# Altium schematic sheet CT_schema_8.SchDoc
size 391 x 238 mm
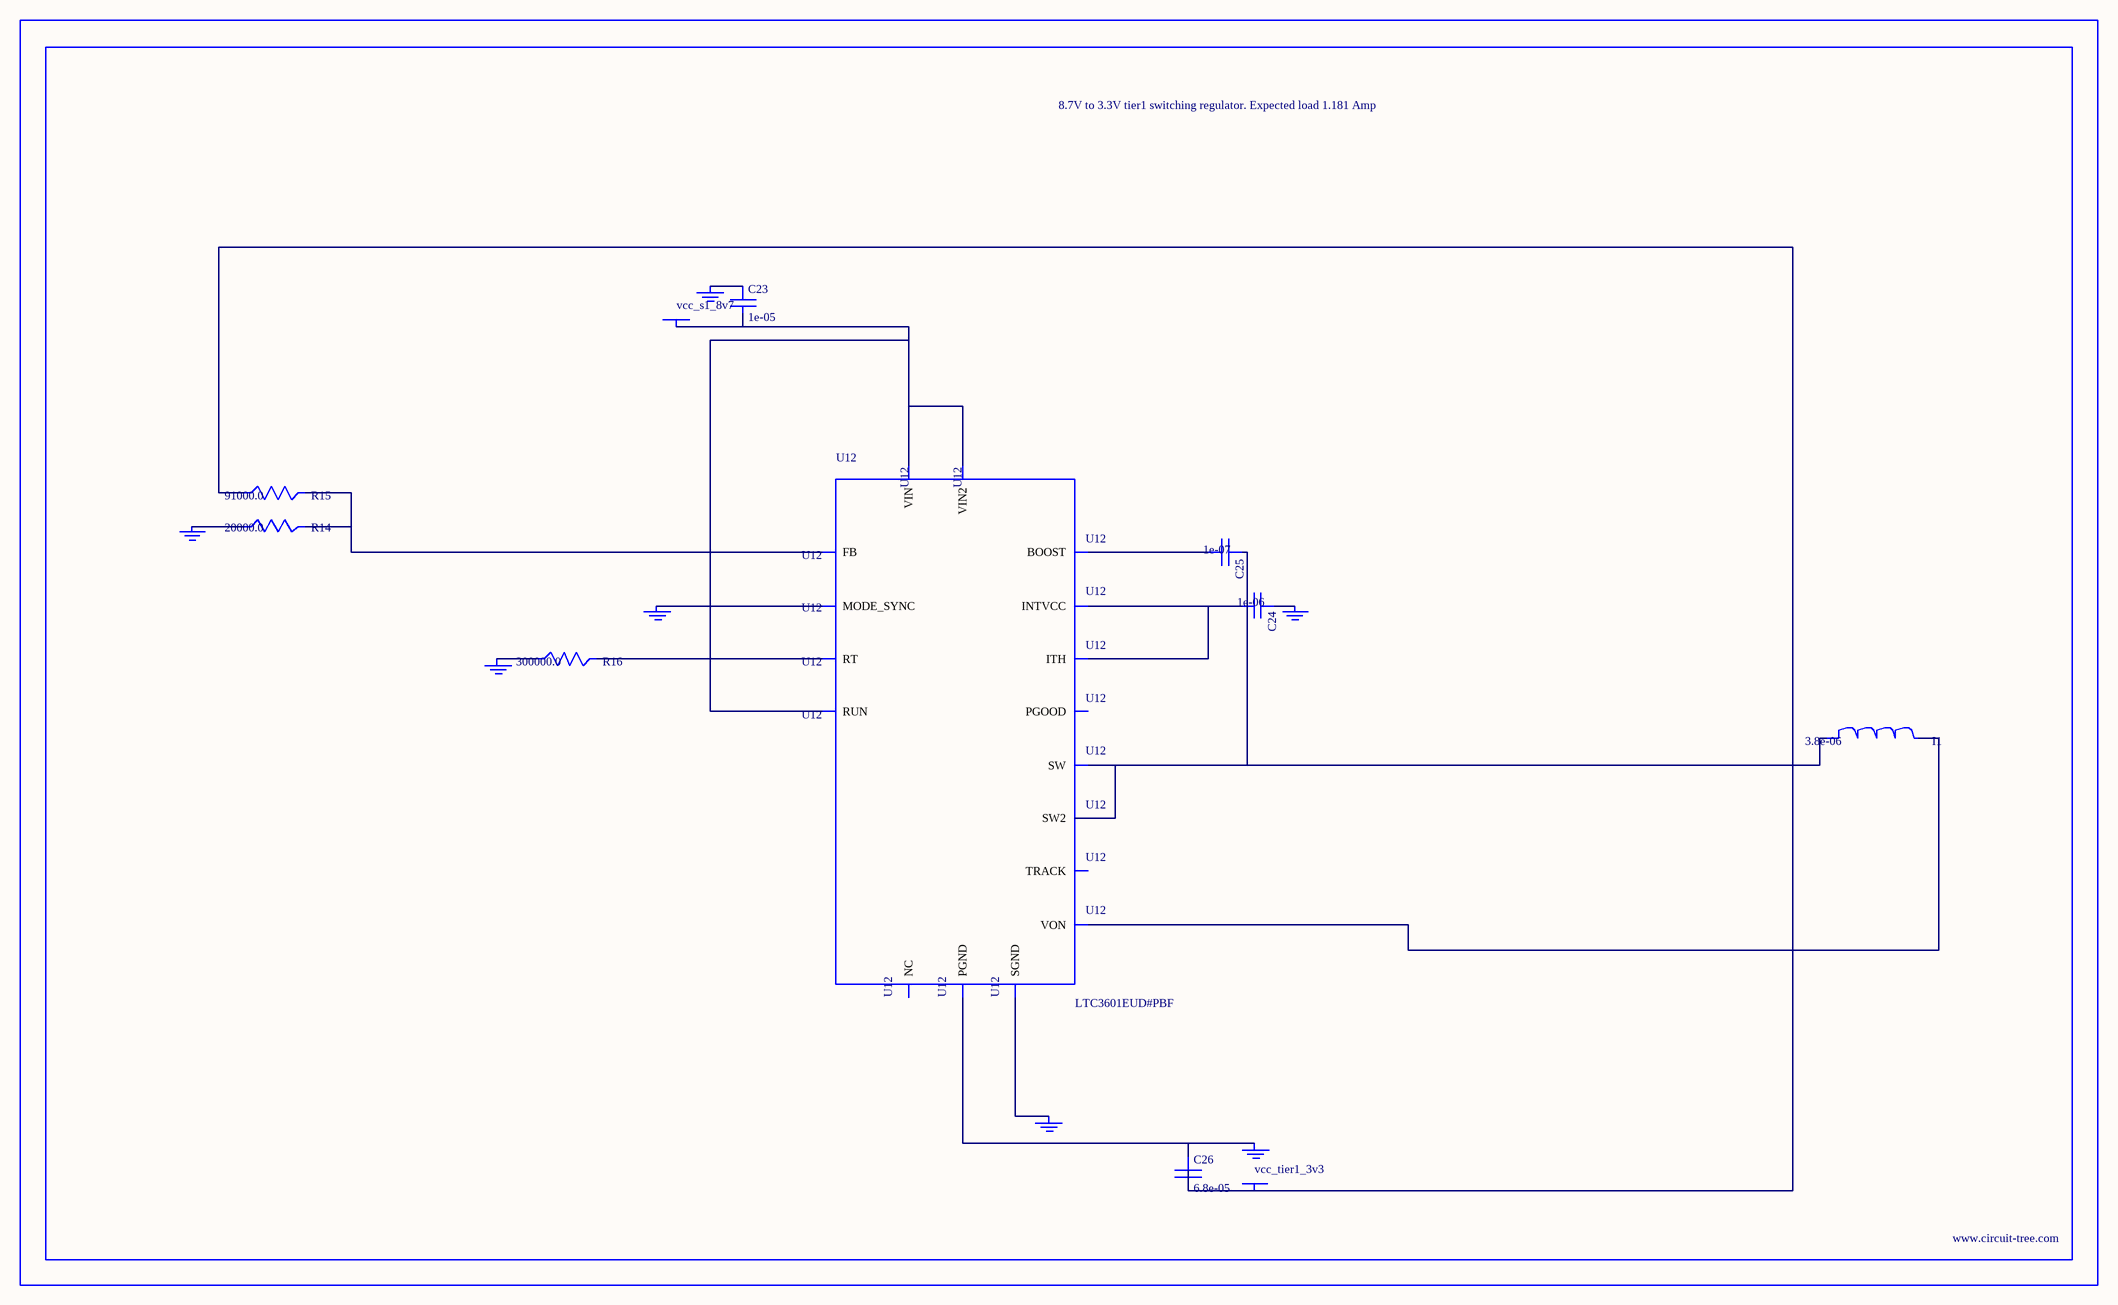
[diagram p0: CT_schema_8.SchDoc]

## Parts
BORDER7  (no value)
C23  1e-05  [C0805]
C24  1e-06  [C0603]
C25  1e-07  [C0402]
C26  6.8e-05  [2220]
GND_INSTANCE_7_0  (no value)
GND_INSTANCE_7_1  (no value)
GND_INSTANCE_7_2  (no value)
GND_INSTANCE_7_3  (no value)
GND_INSTANCE_7_4  (no value)
GND_INSTANCE_7_5  (no value)
GND_INSTANCE_7_6  (no value)
I1  3.8e-06  [DR1040]
POWER_INSTANCE_7_0  vcc_s1_8v7
POWER_INSTANCE_7_1  vcc_tier1_3v3
R14  20000.0  [R0603]
R15  91000.0  [R0603]
R16  300000.0  [R0603]
U12  LTC3601EUD#PBF  [QFN-16_EP]

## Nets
NetC23_1: C23.1 GND_INSTANCE_7_5.0(GND)
NetC23_2: C23.2 POWER_INSTANCE_7_0.0(PWR) U12.14(RUN) U12.15(VIN) U12.16(VIN2)
NetC24_1: C24.1 GND_INSTANCE_7_1.0(GND)
NetC24_2: C24.2 U12.7(INTVCC) U12.12(ITH)
NetC25_1: C25.1 I1.1 U12.3(SW) U12.4(SW2)
NetC25_2: C25.2 U12.6(BOOST)
NetC26_1: C26.1 GND_INSTANCE_7_6.0(GND) U12.17(PGND)
NetC26_2: C26.2 I1.2 POWER_INSTANCE_7_1.0(PWR) R15.1 U12.8(VON)
NetGND_INSTANCE_7_0_0: GND_INSTANCE_7_0.0(GND) U12.1(MODE_SYNC)
NetGND_INSTANCE_7_2_0: GND_INSTANCE_7_2.0(GND) U12.9(SGND)
NetGND_INSTANCE_7_3_0: GND_INSTANCE_7_3.0(GND) R16.1
NetGND_INSTANCE_7_4_0: GND_INSTANCE_7_4.0(GND) R14.1
NetR14_2: R14.2 R15.2 U12.11(FB)
NetR16_2: R16.2 U12.10(RT)

Not connected (* = marked no-connect by the designer): U12 2(PGOOD) 5(NC) 13(TRACK)

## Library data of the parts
BORDER7 = BORDER_PAGE7
C23 = C0805C106K8RACTU
C24 = C0603C105K3RACTU
C25 = C0402C104K3RACTU
C26 = C5750X5R1A686M
GND_INSTANCE_7_0-GND_INSTANCE_7_6 = GND
I1 = DR1040-3R8-R
POWER_INSTANCE_7_0 POWER_INSTANCE_7_1 = PWR
R14 = RC0603JR-0720KL
R15 = RC0603JR-0791KL
R16 = RC0603JR-07300KL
